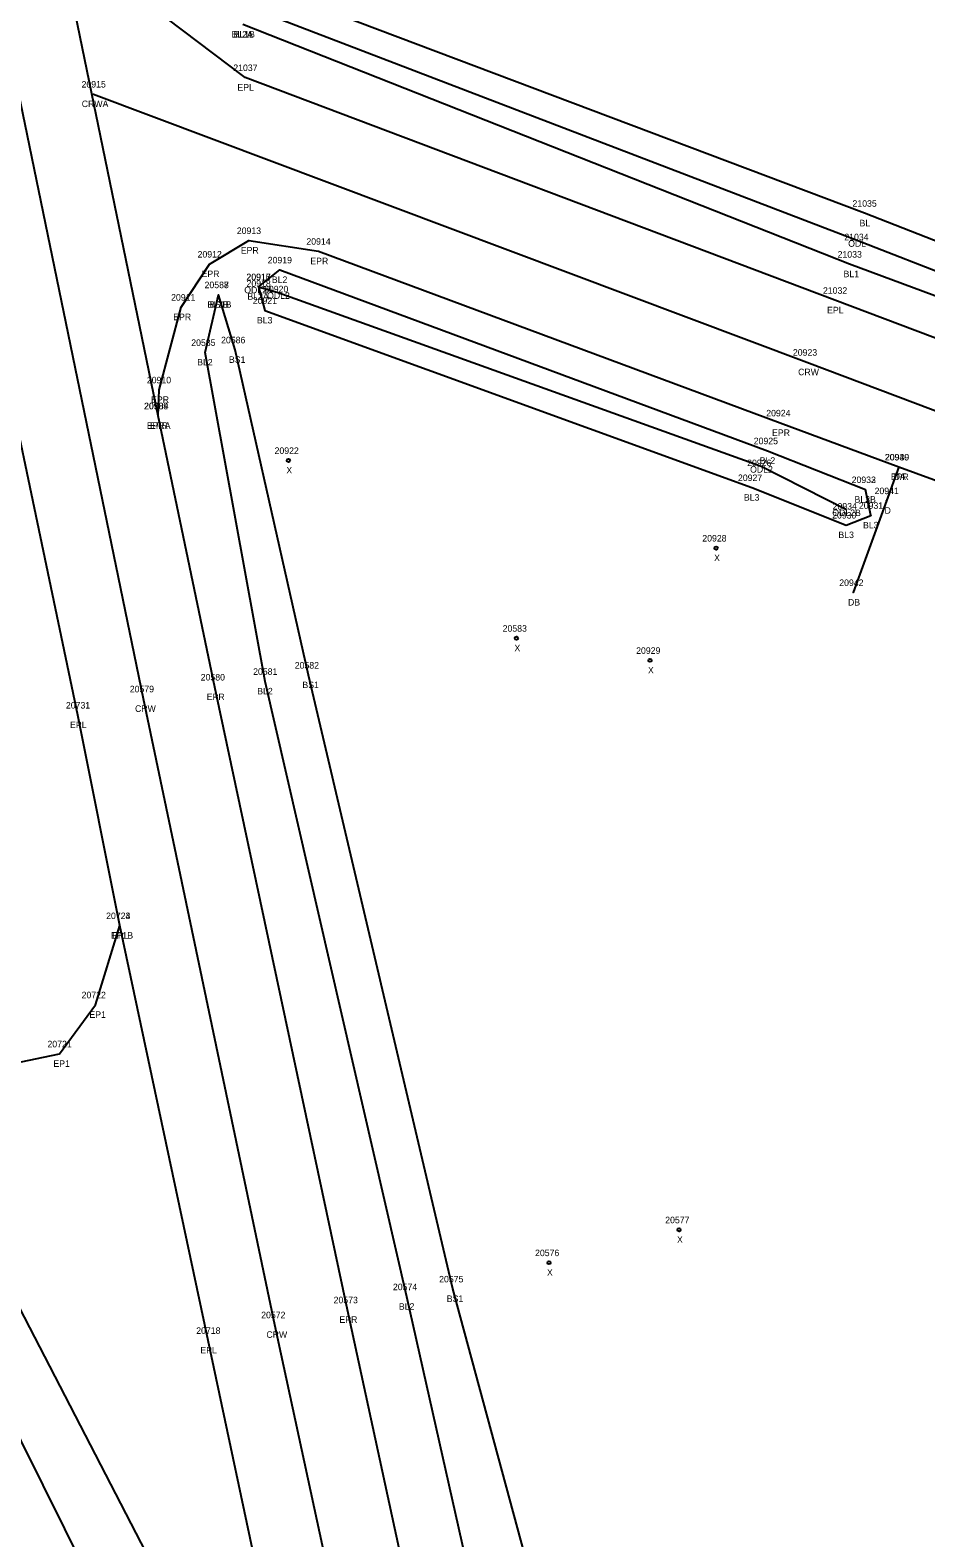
# Model space of a CAD drawing. Extents: x 2522406 to 2524412, y 883189 to 887250.
# Drawn here: x 2523615.6 to 2523753, y 885703.6 to 885934.9 of the extents above; entities that cross this region are included whole.
import ezdxf

# ---------------------------------------------------------------- set-up
doc = ezdxf.new("R2010")
doc.units = 0
for name, color, linetype in [('RD_EX_Bridge_txCode', 7, 'Continuous'), ('RD_EX_Conc_txCode', 7, 'Continuous'), ('RD_EX_DV_Prop_txCode', 7, 'Continuous'), ('RD_EX_DV_PropPin', 7, 'Continuous'), ('RD_EX_Fence_Other_txCode', 7, 'Continuous'), ('RD_EX_GuardRail_txCode', 7, 'Continuous'), ('RD_EX_H2O_txCode', 7, 'Continuous'), ('RD_EX_Road_txCode', 7, 'Continuous'), ('RD_HC_Data', 7, 'Continuous'), ('RD_HC_txCode', 7, 'Continuous'), ('RD_SMD_Locator', 7, 'Continuous')]:
    doc.layers.add(name, color=color, linetype=linetype)

msp = doc.modelspace()

# ---------------------------------------------------------------- linework, layer by layer
at = {"layer": 'RD_EX_Bridge_txCode'}
msp.add_lwpolyline([(2523821.38, 885209.28), (2523799.57, 885259.89), (2523776.94, 885348.57), (2523759.26, 885443.4), (2523731.53, 885544.74), (2523706.15, 885646.77), (2523680.44, 885741.83), (2523658.29, 885836), (2523647.01, 885885.9), (2523644.45, 885894.36)], dxfattribs=at)
at = {"layer": 'RD_EX_Conc_txCode'}
msp.add_lwpolyline([(2523748.84, 885867.93), (2523746.96, 885862.76), (2523741.82, 885848.67)], dxfattribs=at)
at = {"layer": 'RD_EX_Fence_Other_txCode'}
for points in [[(2523781.8, 885156.52), (2523781.78, 885156.93), (2523760.21, 885253.29), (2523740.13, 885343.23), (2523719.19, 885436.78), (2523696.85, 885538.17), (2523674.38, 885637.81), (2523653.13, 885736.33), (2523632.98, 885832.36), (2523612.73, 885930.62), (2523605.3, 885965.87), (2523584.55, 886066.75), (2523565.56, 886163.58), (2523547.1, 886262.85), (2523529.65, 886360.59), (2523513.91, 886459.83), (2523499.26, 886554.51), (2523484.6, 886656.14), (2523471.78, 886751.5), (2523459.33, 886847.49), (2523446.17, 886941.84), (2523432.38, 887043.42), (2523419.16, 887139.29), (2523407.18, 887226.54)], [(2523661.37, 885647.2), (2523594.45, 885776.59), (2523552.23, 885841.47), (2523507.43, 885900.06), (2523441.16, 885972.02), (2523424.24, 885987.72), (2523381.41, 886024.9), (2523343.16, 886054.74), (2523306.49, 886080.61), (2523251.2, 886114.61), (2523207.03, 886139.29), (2523126.81, 886181.72), (2523017.88, 886240.18), (2522926.21, 886288.94), (2522828.62, 886340.37), (2522751.12, 886381.19), (2522643.1, 886438.11), (2522548.62, 886487.92), (2522451.37, 886539.39)], [(2524116.44, 885772.97), (2524066.24, 885791.93), (2524050.42, 885790.77), (2524041.77, 885795.14), (2524005.47, 885808.3), (2523926.79, 885837.24), (2523836.72, 885870.4), (2523743.56, 885906.85), (2523650.98, 885941.85)], [(2524113.56, 885765.5), (2524063.09, 885782.44), (2524039.95, 885789.79), (2524003.49, 885802.18), (2523923.69, 885831.44), (2523834.28, 885864.54), (2523741.28, 885899.04), (2523648.18, 885935.81)], [(2523625.29, 885925.14), (2523734.71, 885884), (2523828.08, 885848.76), (2523918.98, 885814.59), (2524011.29, 885779.29), (2524055.3, 885762.28), (2524103.79, 885742.71)], [(2523650.6, 885895.58), (2523653.86, 885898.16), (2523728.7, 885870.42), (2523743.72, 885864.46)], [(2523650.6, 885895.58), (2523651.56, 885891.95), (2523726.27, 885864.77), (2523740.77, 885859.02), (2523744.54, 885860.51), (2523743.72, 885864.46)], [(2523811.86, 885162.37), (2523808.15, 885172.28), (2523785.79, 885257.41), (2523762.09, 885346.45), (2523739.66, 885439.38), (2523717.11, 885542.61), (2523695.35, 885642.78), (2523673.35, 885740.64), (2523651.61, 885835.04), (2523642.41, 885885.5), (2523644.45, 885894.36)]]:
    msp.add_lwpolyline(points, dxfattribs=at)
at = {"layer": 'RD_EX_GuardRail_txCode'}
for points in [[(2524050.42, 885790.77), (2524041.2, 885792.35), (2524004.66, 885805.26), (2523924.47, 885834.09), (2523835.27, 885866.51), (2523742.31, 885902.71), (2523648.44, 885938.69)], [(2523650.6, 885895.58), (2523653.62, 885894.72), (2523727.71, 885868.06), (2523740.79, 885861.4)]]:
    msp.add_lwpolyline(points, dxfattribs=at)
at = {"layer": 'RD_EX_H2O_txCode'}
for points in [[(2523792.89, 885158.83), (2523792.78, 885159.31), (2523771.24, 885254.79), (2523751.35, 885344.92), (2523730.54, 885437.51), (2523707.6, 885540.62), (2523685.46, 885640.59), (2523664.24, 885738.63), (2523643.89, 885834.17), (2523635.19, 885875.78), (2523616.17, 885968.17), (2523612.48, 885987.85), (2523604.72, 886024.35), (2523595.57, 886068.72), (2523589.05, 886102.26), (2523582.94, 886131.85), (2523576.68, 886165.74), (2523558.47, 886264.98), (2523540.97, 886362.67), (2523524.95, 886461.52), (2523510.61, 886556.01)], [(2523770.8, 885154.29), (2523771.58, 885154.56), (2523750.32, 885250.18), (2523730.02, 885340.63), (2523709.49, 885433.05), (2523684.65, 885542.45), (2523664.08, 885635.88), (2523651.44, 885693.73), (2523642.88, 885733.94), (2523629.35, 885797.57), (2523622.9, 885829.87), (2523606.11, 885909.71), (2523592.26, 885976.2), (2523574.44, 886065.16), (2523555.22, 886162.6), (2523537.13, 886260.64), (2523519.81, 886359.06), (2523504.07, 886456.63), (2523489.21, 886553.34)], [(2523684.65, 885542.45), (2523665.3, 885601.29), (2523637.58, 885671.41), (2523607.52, 885731.93), (2523601.98, 885741.93), (2523543.26, 885835.23), (2523498.93, 885892.88), (2523468.29, 885928.45), (2523427.21, 885969.98), (2523382.58, 886009.7), (2523334.28, 886047.25), (2523293.16, 886075.95), (2523246.15, 886104.75), (2523196.47, 886132.32), (2523113.8, 886176.8), (2523099.27, 886184.43), (2523034.38, 886218.94), (2522922.92, 886277.95), (2522823.46, 886330.29), (2522745.54, 886371.87), (2522637.62, 886428.52), (2522542.73, 886478.54), (2522445.74, 886530.11)], [(2524107.9, 885752.1), (2524059.47, 885771.52), (2524001.2, 885793.95), (2523921.69, 885824.36), (2523831.94, 885858.45), (2523739.04, 885893.5), (2523648.58, 885927.67), (2523634.12, 885938.58), (2523623.76, 885951), (2523616.17, 885968.17)], [(2523635.19, 885875.78), (2523635.36, 885879.76), (2523638.75, 885892.45), (2523643.09, 885899.06), (2523649.11, 885902.67), (2523659.79, 885901.03), (2523730.62, 885874.69), (2523748.84, 885867.93), (2523768.03, 885860.93), (2523824.53, 885839.24), (2523915.56, 885805.2), (2524007.47, 885770.01), (2524051.18, 885752.64), (2524099.87, 885733.59)], [(2523603.68, 885782.32), (2523612.99, 885776.42), (2523620.06, 885777.9), (2523625.59, 885785.42), (2523629.35, 885797.57)]]:
    msp.add_lwpolyline(points, dxfattribs=at)
at = {"layer": 'RD_SMD_Locator'}
for centre, radius in [((2523648.58, 885927.67), 0.001), ((2523625.29, 885925.14), 0.001), ((2523743.56, 885906.85), 0.001), ((2523649.11, 885902.67), 0.001), ((2523742.31, 885902.71), 0.001), ((2523659.79, 885901.03), 0.001), ((2523643.09, 885899.06), 0.001), ((2523653.86, 885898.16), 0.001), ((2523741.28, 885899.04), 0.001), ((2523650.6, 885895.58), 0.001), ((2523650.6, 885895.58), 0.001), ((2523650.6, 885895.58), 0.001), ((2523644.45, 885894.36), 0.001), ((2523644.45, 885894.36), 0.001), ((2523653.62, 885894.72), 0.001), ((2523739.04, 885893.5), 0.001), ((2523638.75, 885892.45), 0.001), ((2523651.56, 885891.95), 0.001), ((2523642.41, 885885.5), 0.001), ((2523647.01, 885885.9), 0.001), ((2523734.71, 885884), 0.001), ((2523635.36, 885879.76), 0.001), ((2523635.19, 885875.78), 0.001), ((2523635.19, 885875.78), 0.001), ((2523730.62, 885874.69), 0.001), ((2523728.7, 885870.42), 0.001), ((2523655.19, 885868.93), 0.25), ((2523727.71, 885868.06), 0.001), ((2523748.84, 885867.93), 0.001), ((2523748.84, 885867.93), 0.001), ((2523726.27, 885864.77), 0.001), ((2523743.72, 885864.46), 0.001), ((2523743.72, 885864.46), 0.001), ((2523740.79, 885861.4), 0.001), ((2523746.96, 885862.76), 0.001), ((2523740.77, 885859.02), 0.001), ((2523744.54, 885860.51), 0.001), ((2523720.81, 885855.49), 0.25), ((2523741.82, 885848.67), 0.001), ((2523690.18, 885841.66), 0.25), ((2523710.66, 885838.26), 0.25), ((2523658.29, 885836), 0.001), ((2523643.89, 885834.17), 0.001), ((2523651.61, 885835.04), 0.001), ((2523632.98, 885832.36), 0.001), ((2523622.9, 885829.87), 0.001), ((2523629.35, 885797.57), 0.001), ((2523629.35, 885797.57), 0.001), ((2523625.59, 885785.42), 0.001), ((2523620.06, 885777.9), 0.001), ((2523715.12, 885750.91), 0.25), ((2523695.17, 885745.86), 0.25), ((2523673.35, 885740.64), 0.001), ((2523680.44, 885741.83), 0.001), ((2523664.24, 885738.63), 0.001), ((2523653.13, 885736.33), 0.001), ((2523642.88, 885733.94), 0.001)]:
    msp.add_circle(centre, radius, dxfattribs=at)

# ---------------------------------------------------------------- texts
at = {"layer": 'RD_EX_DV_Prop_txCode'}
for s, p in [('20922', (2523653.07, 885869.93)), ('X', (2523654.88, 885866.93)), ('20928', (2523718.69, 885856.49)), ('X', (2523720.5, 885853.49)), ('20583', (2523688.06, 885842.66)), ('X', (2523689.87, 885839.66)), ('20929', (2523708.54, 885839.26)), ('X', (2523710.35, 885836.26)), ('20577', (2523713, 885751.91)), ('X', (2523714.81, 885748.91)), ('20576', (2523693.03, 885746.86)), ('X', (2523694.86, 885743.86))]:
    msp.add_text(s, height=1, dxfattribs=at).set_placement(p)
at = {"layer": 'RD_EX_DV_PropPin'}
for s, p in [('21034', (2523740.48, 885902.71)), ('ODL', (2523741.07, 885901.71)), ('ODL2A', (2523648.42, 885894.58)), ('20918', (2523648.77, 885895.58)), ('20920', (2523651.46, 885894.72)), ('ODL2', (2523651.92, 885893.72)), ('20926', (2523725.57, 885868.06)), ('ODL2', (2523726.02, 885867.06)), ('ODL2B', (2523738.63, 885860.4)), ('20934', (2523738.68, 885861.4))]:
    msp.add_text(s, height=1, dxfattribs=at).set_placement(p)
at = {"layer": 'RD_EX_Road_txCode'}
for s, p in [('20940', (2523746.68, 885868.93)), ('DA', (2523748.04, 885865.93)), ('20941', (2523745.12, 885863.76)), ('D', (2523746.65, 885860.76)), ('20942', (2523739.7, 885849.67)), ('DB', (2523741.04, 885846.67))]:
    msp.add_text(s, height=1, dxfattribs=at).set_placement(p)
at = {"layer": 'RD_HC_Data'}
for s, p in [('21037', (2523646.74, 885928.67)), ('EPL', (2523647.37, 885925.67)), ('20913', (2523647.28, 885903.67)), ('20914', (2523657.95, 885902.03)), ('20912', (2523641.26, 885900.06)), ('EPR', (2523647.89, 885900.67)), ('EPR', (2523658.56, 885899.03)), ('EPR', (2523641.87, 885897.06)), ('21032', (2523737.2, 885894.5)), ('20911', (2523637.2, 885893.45)), ('EPR', (2523637.52, 885890.45)), ('EPL', (2523737.83, 885891.5)), ('20910', (2523633.48, 885880.76)), ('20909', (2523633.03, 885876.78)), ('20584', (2523633.07, 885876.78)), ('EPR', (2523634.13, 885877.76)), ('EPRA', (2523633.47, 885873.78)), ('EPR', (2523633.96, 885873.78)), ('20924', (2523728.5, 885875.69)), ('EPR', (2523729.39, 885872.69)), ('20939', (2523746.72, 885868.93)), ('EPR', (2523747.61, 885865.93)), ('20580', (2523641.74, 885835.17)), ('EPR', (2523642.67, 885832.17)), ('20731', (2523621.06, 885830.87)), ('EPL', (2523621.69, 885827.87)), ('20723', (2523627.23, 885798.57)), ('20724', (2523627.23, 885798.57)), ('EP1B', (2523627.95, 885795.57)), ('EPL', (2523628.14, 885795.57)), ('20722', (2523623.47, 885786.42)), ('EP1', (2523624.67, 885783.42)), ('20721', (2523618.23, 885778.9)), ('EP1', (2523619.14, 885775.9)), ('20573', (2523662.13, 885739.63)), ('20718', (2523641.05, 885734.94)), ('EPR', (2523663.02, 885736.63)), ('EPL', (2523641.68, 885731.94))]:
    msp.add_text(s, height=1, dxfattribs=at).set_placement(p)
at = {"layer": 'RD_HC_txCode'}
for s, p in [('BL2A', (2523646.48, 885933.81)), ('BL1B', (2523646.78, 885933.81)), ('20915', (2523623.46, 885926.14)), ('CRWA', (2523623.49, 885923.14)), ('21035', (2523741.73, 885907.85)), ('BL', (2523742.81, 885904.85)), ('20919', (2523652.02, 885899.16)), ('21033', (2523739.45, 885900.04)), ('20916', (2523648.74, 885896.58)), ('20917', (2523648.77, 885896.58)), ('BL1', (2523740.36, 885897.04)), ('20587', (2523642.33, 885895.36)), ('20588', (2523642.33, 885895.36)), ('BL2', (2523652.65, 885896.16)), ('BL2B', (2523642.77, 885892.36)), ('BS1B', (2523643.03, 885892.36)), ('BL2A', (2523648.91, 885893.58)), ('BL3A', (2523648.91, 885893.58)), ('20921', (2523649.73, 885892.95)), ('BL3', (2523650.36, 885889.95)), ('20585', (2523640.29, 885886.5)), ('20586', (2523644.87, 885886.9)), ('20923', (2523732.59, 885885)), ('BL2', (2523641.2, 885883.5)), ('BS1', (2523646.07, 885883.9)), ('CRW', (2523733.39, 885882)), ('20925', (2523726.58, 885871.42)), ('BL2', (2523727.49, 885868.42)), ('20927', (2523724.16, 885865.77)), ('20932', (2523741.6, 885865.46)), ('20933', (2523741.6, 885865.46)), ('BL3', (2523725.07, 885862.77)), ('BL3B', (2523742.04, 885862.46)), ('BL2B', (2523742.04, 885862.46)), ('20930', (2523738.61, 885860.02)), ('20931', (2523742.71, 885861.51)), ('BL3', (2523743.34, 885858.51)), ('BL3', (2523739.57, 885857.02)), ('20582', (2523656.17, 885837)), ('20581', (2523649.78, 885836.04)), ('20579', (2523630.86, 885833.36)), ('BL2', (2523650.41, 885833.04)), ('BS1', (2523657.34, 885834)), ('CRW', (2523631.66, 885830.36)), ('20574', (2523671.23, 885741.64)), ('20575', (2523678.32, 885742.83)), ('BS1', (2523679.49, 885739.83)), ('20572', (2523651.02, 885737.33)), ('BL2', (2523672.14, 885738.64)), ('CRW', (2523651.82, 885734.33))]:
    msp.add_text(s, height=1, dxfattribs=at).set_placement(p)

doc.saveas('drawing.dxf')
